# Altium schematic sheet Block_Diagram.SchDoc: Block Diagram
size A4; DrawnBy: Siddhant Jajoo; Organization: Team - Ashwathama; Address1: Colorado Boulder; Address2: Author : Siddhant Jajoo; Address3: Self Checkout Shopping Cart; DocumentNumber: 1; Revision: 1.0; SheetNumber: 0; SheetTotal: 7
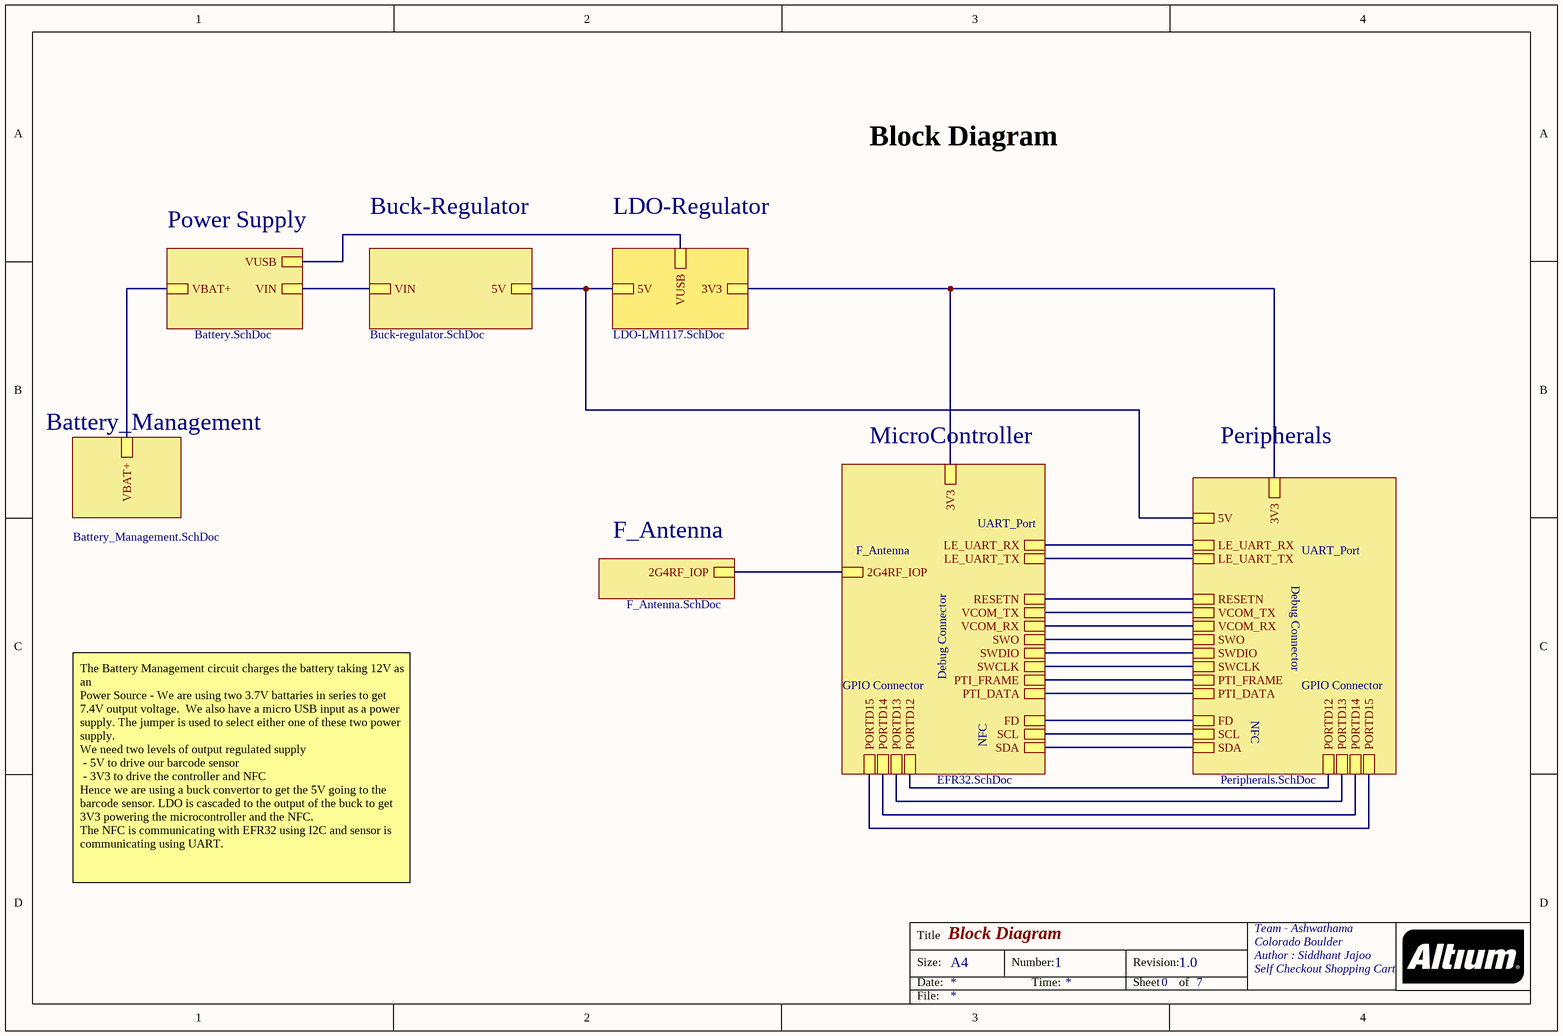
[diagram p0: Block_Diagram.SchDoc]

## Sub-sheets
Battery_Management = Battery_Management.SchDoc: VBAT+
Buck-Regulator = Buck-regulator.SchDoc: VIN, 5V
F_Antenna = F_Antenna.SchDoc: 2G4RF_IOP
LDO-Regulator = LDO-LM1117.SchDoc: 3V3, 5V, VUSB
MicroController = EFR32.SchDoc: LE_UART_RX, LE_UART_TX, 2G4RF_IOP, SCL, SDA, 3V3, FD, RESETN, VCOM_TX, VCOM_RX, PTI_FRAME, PTI_DATA, SWO, SWDIO, SWCLK, PORTD12, PORTD13, PORTD14, PORTD15
Peripherals = Peripherals.SchDoc: PTI_FRAME, SWDIO, VCOM_TX, RESETN, FD, VCOM_RX, SWO, SWCLK, PTI_DATA, SCL, SDA, 3V3, LE_UART_RX, LE_UART_TX, 5V, PORTD12, PORTD13, PORTD14, PORTD15
Power Supply = Battery.SchDoc: VBAT+, VIN, VUSB

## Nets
(unnamed): sheet Buck-Regulator/VIN, sheet Power Supply/VIN
(unnamed): sheet Buck-Regulator/5V, sheet LDO-Regulator/5V, sheet Peripherals/5V  [a separate net that carries the same name]
(unnamed): sheet LDO-Regulator/3V3, sheet Peripherals/3V3, sheet MicroController/3V3  [a separate net that carries the same name]
(unnamed): sheet LDO-Regulator/VUSB, sheet Power Supply/VUSB  [a separate net that carries the same name]
(unnamed): sheet F_Antenna/2G4RF_IOP, sheet MicroController/2G4RF_IOP  [a separate net that carries the same name]
(unnamed): sheet Peripherals/PTI_FRAME, sheet MicroController/PTI_FRAME  [a separate net that carries the same name]
(unnamed): sheet Peripherals/SWDIO, sheet MicroController/SWDIO  [a separate net that carries the same name]
(unnamed): sheet Peripherals/VCOM_TX, sheet MicroController/VCOM_TX  [a separate net that carries the same name]
(unnamed): sheet Peripherals/RESETN, sheet MicroController/RESETN  [a separate net that carries the same name]
(unnamed): sheet Peripherals/FD, sheet MicroController/FD  [a separate net that carries the same name]
(unnamed): sheet Peripherals/VCOM_RX, sheet MicroController/VCOM_RX  [a separate net that carries the same name]
(unnamed): sheet Peripherals/SWO, sheet MicroController/SWO  [a separate net that carries the same name]
(unnamed): sheet Peripherals/SWCLK, sheet MicroController/SWCLK  [a separate net that carries the same name]
(unnamed): sheet Peripherals/PTI_DATA, sheet MicroController/PTI_DATA  [a separate net that carries the same name]
(unnamed): sheet Peripherals/SCL, sheet MicroController/SCL  [a separate net that carries the same name]
(unnamed): sheet Peripherals/SDA, sheet MicroController/SDA  [a separate net that carries the same name]
(unnamed): sheet Peripherals/LE_UART_RX, sheet MicroController/LE_UART_RX  [a separate net that carries the same name]
(unnamed): sheet Peripherals/LE_UART_TX, sheet MicroController/LE_UART_TX  [a separate net that carries the same name]
(unnamed): sheet Peripherals/PORTD12, sheet MicroController/PORTD12  [a separate net that carries the same name]
(unnamed): sheet Peripherals/PORTD13, sheet MicroController/PORTD13  [a separate net that carries the same name]
(unnamed): sheet Peripherals/PORTD14, sheet MicroController/PORTD14  [a separate net that carries the same name]
(unnamed): sheet Peripherals/PORTD15, sheet MicroController/PORTD15  [a separate net that carries the same name]
(unnamed): sheet Power Supply/VBAT+, sheet Battery_Management/VBAT+  [a separate net that carries the same name]

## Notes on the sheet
- Block Diagram
- F_Antenna
- UART_Port
- Debug Connector
- GPIO Connector
- NFC
- The Battery Management circuit charges the battery taking 12V as an
  Power Source - We are using two 3.7V battaries in series to get 7.4V output voltage.  We also have a micro USB input as a power supply. The jumper is used to select either one of these two power supply.
  We need two levels of output regulated supply
  - 5V to drive our barcode sensor
  - 3V3 to drive the controller and NFC
  Hence we are using a buck convertor to get the 5V going to the barcode sensor. LDO is cascaded to the output of the buck to get 3V3 powering the microcontroller and the NFC.
  The NFC is communicating with EFR32 using I2C and sensor is communicating using UART.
